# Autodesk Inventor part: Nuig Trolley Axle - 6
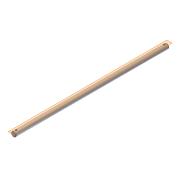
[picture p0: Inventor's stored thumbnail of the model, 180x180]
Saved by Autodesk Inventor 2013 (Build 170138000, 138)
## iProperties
Shininess: 64.0
Length Units: 11269
Angle Units: 11279
Time Units: 11290
Mass Units: 11286
Length Display Precision: 3
Angle Display Precision: 2
Created: 2002-08
Part Number: Nuig Trolley Axle - 6
Document SubType Name: Modeling
Designer: kalamea
Density: 1 g/cm^3
Material: Generic
Density: 0.0
Volumn: 0.0
Area: 0.0
PropertySet Name: Model Information
Control State: 0
Master: False
Checked Out: False
Author: kalamea
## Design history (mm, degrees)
sketch "Sketch1"
  geometry: C1 r 9.525 at (0, 0); 1 further point
  constraints: 1 centre point, 1 coincident
  dimensions: "d0" = 19.05 diameter of C1
extrude "Extrusion1" new body sketch "Sketch1" stored distance "d1" = 600; taper "d2" = 0 deg
chamfer "Chamfer1" distance "d3" = 1.588; stored, may be unused: second distance "d4" = 1.588, angle "d5" = 45 deg
workplane "Work Plane1"
sketch "Sketch2"
  geometry: L1 (-7.937, 300)-(7.937, 300) reference; C1 r 3 at (0, 290); 1 further point
  constraints: 1 centre point, 1 midpoint, 1 vertical alignment
  dimensions: "d6" = 6 diameter of C1; "d7" = 10 distance from line of L1 C1.centre
extrude "Extrusion2" cut sketch "Sketch2" stored distance "d8" = 10; taper "d9" = 0 deg
mirror "Mirror1"
body "Solid1"
